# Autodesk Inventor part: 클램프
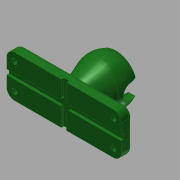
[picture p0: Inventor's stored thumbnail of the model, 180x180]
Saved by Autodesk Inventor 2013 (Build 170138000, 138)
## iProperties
Created: 2017-10
Part Number: 클램프
Material: ABS 플라스틱
Document SubType Name: Modeling
Designer: mduedu
Density: 1 g/cm^3
Author: mduedu
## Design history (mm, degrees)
sketch "스케치1"
  geometry: L1 (-22, -8)-(22, -8); L2 (22, -8)-(22, 8); L3 (22, 8)-(-22, 8); L4 (-22, 8)-(-22, -8); L5 (-22, -8)-(22, 8); L6 (22, -8)-(-22, 8); 1 further point
  constraints: 12 end point, 2 midpoint, 2 parallel, 1 horizontal, 1 perpendicular
  dimensions: "d0" = 44 distance of L3.end L2.end; "d1" = 16 distance of L2.end L1.end
extrude "돌출1" new body sketch "스케치1" distance "d2" = 4; taper "d3" = 0 deg
sketch "스케치2"
  geometry: L1 (9, -12)-(-9, -12); L2 (-8, 0)-(8, 0) reference; A1 r 9 centre (0, -12) between (9, -12) and (-9, -12); 3 further points
  constraints: 3 midpoint, 2 end point, 2 point on circle, 1 centre point, 1 horizontal, 1 vertical alignment
  dimensions: "d4" = 18 diameter of A1; "d6" = 12 distance from line of A1.centre L2
revolve "회전1" sketch "스케치2" stored, may be unused: angle "d5" = 90 deg
sketch "스케치6"
  geometry: L1 (0, 0)-(0, -12); L2 (0, -12)-(9, -12); L3 (5, 0)-(8.391, -8.746); L4 (0, 0)-(5, 0); A1 r 9 centre (0, -12) between (9, -12) and (8.391, -8.746) reference
  constraints: 8 end point, 2 point on circle, 1 parallel, 1 perpendicular, 1 tangent, 1 vertical
  dimensions: "d19" = 10 diameter of L3.start L1
revolve "회전3" sketch "스케치6" stored, may be unused: angle "d22" = 90 deg
sketch "스케치3"
  geometry: L1 (7, -12)-(-7, -12); L2 (8, 0)-(-8, 0) reference; L3 (8.062, -16)-(-8.062, -16); A1 r 7 centre (0, -12) between (7, -12) and (-7, -12); A2 r 9 centre (0, -12) between (8.062, -16) and (-8.062, -16) reference; 4 further points
  constraints: 4 end point, 4 point on circle, 3 midpoint, 1 centre point, 1 coincident, 1 concentric, 1 horizontal, 1 parallel, 1 vertical alignment
  dimensions: "d7" = 14 diameter of A1; "d10" = 4 distance between parallel lines of L3 L1
revolve "회전2" stored, may be unused: angle "d8" = 90 deg
feature "돌출 곡면2" dims "d23" = 50, "d24" = 0
feature "분할2"
node "작업점1"
sketch "스케치7"
  geometry: L1 (3, -16)-(-3, -16); L2 (-3, -16)-(-3, -13); L3 (3, -13)-(3, -16); L4 (-5.745, -16)-(5.745, -16) reference; A1 r 3 centre (0, -13) between (3, -13) and (-3, -13); 2 further points
  constraints: 6 end point, 2 point on circle, 2 tangent, 1 centre point, 1 coincident, 1 collinear, 1 horizontal, 1 parallel, 1 perpendicular, 1 vertical alignment
  dimensions: "d25" = 6 diameter of A1; "d30" = 3 distance from line of point (0, -13) L1
extrude "돌출2" cut sketch "스케치7" stored distance "d28" = 50; taper "d29" = 0 deg
fillet "모깎기1" dims "d31" = 0.5
sketch "스케치8"
  geometry: L1 (-5, 0)-(-8.391, -8.746) reference; L2 (-22, 0)-(22, 0) reference; L3 (-7.495, -6.434)-(-12, 0); 1 further point
  constraints: 2 end point, 2 point on line
  dimensions: "d32" = 12 distance of L3.end point (0, 0); "d33" = 55 deg angle of L3 L2
feature "리브1" sketch "스케치8" dims "d34" = 1, "d35" = 3, "d36" = 0, "d37" = 0, "d38" = 1, "d39" = 1
fillet "모깎기2" dims "d40" = 1
fillet "모깎기3" dims "d41" = 1
fillet "모깎기4" dims "d42" = 1
sketch "스케치9"
  geometry: L1 (22, -8)-(22, 8) reference; L2 (22, 8)-(-22, 8) reference; L3 (-22, 8)-(-22, -8) reference; L4 (-22, -8)-(22, -8) reference; L5 (-22, 1)-(22, 1); L6 (22, 1)-(22, -1); L7 (22, -1)-(-22, -1); L8 (-22, -1)-(-22, 1); L9 (-1, 8)-(1, 8); L10 (1, 8)-(1, -8); L11 (1, -8)-(-1, -8); L12 (-1, -8)-(-1, 8); 3 further points
  constraints: 16 end point, 4 parallel, 4 point on line, 2 horizontal, 2 midpoint, 2 perpendicular, 1 horizontal alignment, 1 vertical alignment
  dimensions: "d43" = 2 distance between parallel lines of L7 L5; "d45" = 2 distance between parallel lines of L10 L12
extrude "돌출3" cut sketch "스케치9" distance "d46" = 1; taper "d47" = 0 deg
fillet "모깎기5" dims "d48" = 1
fillet "모깎기6" dims "d49" = 3
fillet "모깎기7" dims "d50" = 1
sketch "스케치10"
  geometry: C1 r 1 at (-19, 5); C2 r 1 at (19, 5); C3 r 1 at (19, -5); C4 r 1 at (-19, -5); A1 r 3 centre (-19, 5) between (-19, 8) and (-22, 5) reference; A2 r 3 centre (19, 5) between (22, 5) and (19, 8) reference; A3 r 3 centre (19, -5) between (19, -8) and (22, -5) reference; A4 r 3 centre (-19, -5) between (-22, -5) and (-19, -8) reference; 1 further point
  constraints: 4 centre point, 4 coincident, 3 equal radius
  dimensions: "d51" = 2 diameter of C1
extrude "돌출4" cut sketch "스케치10" stored distance "d52" = 1; taper "d53" = 0 deg
node "솔리드1"
mirror "대칭1"
node "곡면2"
node "투영된 루프1"
